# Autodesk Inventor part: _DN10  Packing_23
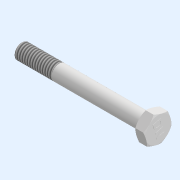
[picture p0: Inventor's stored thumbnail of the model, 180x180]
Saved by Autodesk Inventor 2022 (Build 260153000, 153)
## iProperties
Created: 2021-12
Part Number: _DN10  Packing_23
Material: Generico
Document SubType Name: Modeling
Designer: admin
Density: 1 g/cm^3
Appearance: Default
Author: admin
Revision Number: NONE
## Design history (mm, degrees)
node "_DN10  Packing"
sketch "Schizzo1"
  geometry: C1 r 3 at (0, 0) reference; 1 further point
extrude "Estrusione1" join sketch "Schizzo1" distance "d2" = 6; taper "d3" = 0 deg
feature "Filettatura2" dims "d4" = 15, "d5" = 0
chamfer "Smusso1" distance "d6" = 0.4; stored, may be unused: second distance "d7" = 2, angle "d8" = 45 deg
node "Solido1"
node "Linea chiusa proiettata1"
